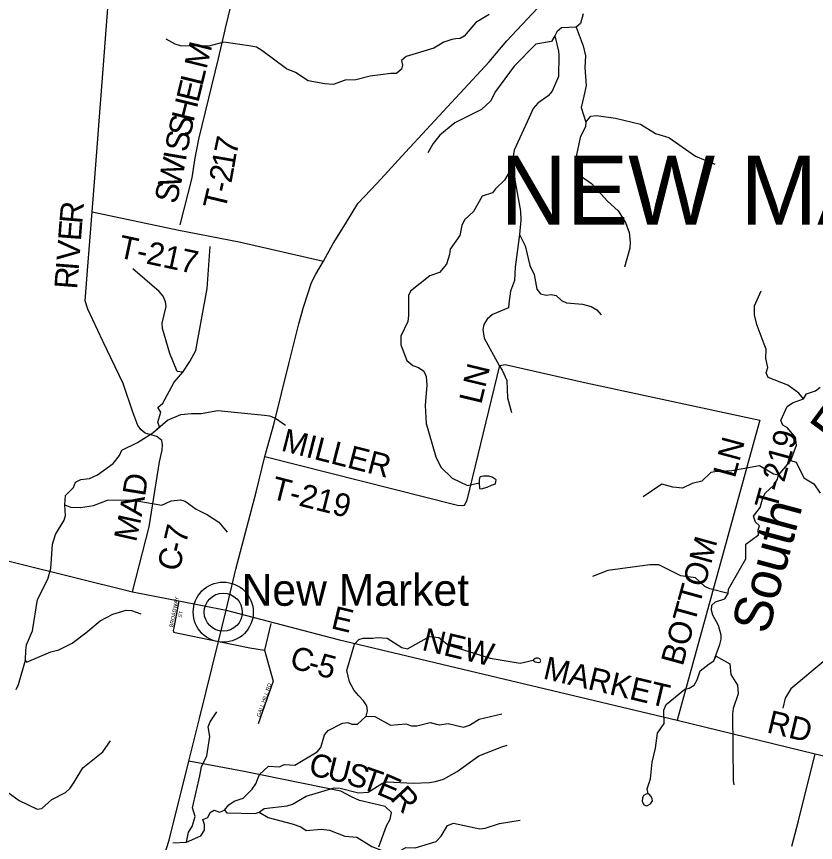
# Model space of a CAD drawing. Extents: x 1525783 to 1900577, y 218250 to 627376.
# Drawn here: x 1634317 to 1644767, y 412684 to 423483 of the extents above; entities that cross this region are included whole.
import ezdxf

# ---------------------------------------------------------------- set-up
doc = ezdxf.new("R2010")
doc.units = 0
for name, color, linetype in [('GM_X_County_Road', 7, 'Continuous'), ('GM_X_County_Road_Text', 7, 'Continuous'), ('GM_X_Minor_Lake', 7, 'Continuous'), ('GM_X_Minor_River', 7, 'Continuous'), ('GM_X_Minor_River_Text', 7, 'Continuous'), ('GM_X_Township_Road', 7, 'Continuous'), ('GM_X_Township_Road_Text', 7, 'Continuous'), ('GM_X_Township_ROW', 7, 'Continuous'), ('GM_X_Township_Subdivision', 7, 'Continuous'), ('GM_X_Township_Subdivision_Text', 7, 'Continuous'), ('GM_X_Township_Text', 7, 'Continuous'), ('GM_X_Unincorporated', 7, 'Continuous'), ('GM_X_Unincorporated_Location', 7, 'Continuous'), ('GM_X_Unincorporated_Text', 7, 'Continuous'), ('GM_X_US_Route', 7, 'Continuous')]:
    doc.layers.add(name, color=color, linetype=linetype)

msp = doc.modelspace()

# ---------------------------------------------------------------- linework, layer by layer
at = {"layer": 'GM_X_County_Road'}
for points in [[(1635835, 415961), (1636054, 416812), (1636189, 417660), (1636221, 417814), (1636227, 417882), (1636219, 417938), (1636154, 417994), (1636001, 418035), (1635948, 418078), (1635903, 418134), (1635838, 418312), (1635713, 418683), (1635446, 419238), (1635252, 419658), (1635217, 419764), (1635246, 420162), (1635307, 420930), (1635348, 421429), (1635515, 423648)], [(1631793, 415765), (1631793, 415765), (1631953, 416522), (1631988, 416688), (1632010, 416780), (1632047, 416831), (1632214, 416828), (1633533, 416532), (1635835, 415961), (1636440, 415843), (1637058, 415721)], [(1637058, 415721), (1637058, 415721), (1638525, 415336), (1642958, 414285), (1644763, 413844), (1647257, 413258)]]:
    msp.add_lwpolyline(points, dxfattribs=at)
at = {"layer": 'GM_X_Minor_Lake'}
for points in [[(1640393, 417306), (1640443, 417322), (1640473, 417331), (1640530, 417357), (1640580, 417374), (1640590, 417424), (1640539, 417459), (1640495, 417473), (1640425, 417472), (1640381, 417463), (1640371, 417447), (1640366, 417417), (1640368, 417387)], [(1640368, 417387), (1640374, 417311), (1640393, 417306)], [(1641075, 415068), (1641089, 415052), (1641101, 415046), (1641121, 415040), (1641147, 415035), (1641165, 415043), (1641173, 415057), (1641161, 415085), (1641138, 415094), (1641112, 415092), (1641099, 415088), (1641079, 415074)], [(1641079, 415074), (1641075, 415068)], [(1642553, 413317), (1642537, 413309), (1642519, 413297), (1642504, 413263), (1642500, 413223), (1642521, 413175), (1642563, 413164), (1642607, 413190), (1642634, 413229), (1642632, 413256), (1642616, 413286)], [(1642616, 413286), (1642592, 413315), (1642578, 413320), (1642553, 413317)]]:
    msp.add_lwpolyline(points, dxfattribs=at)
at = {"layer": 'GM_X_Minor_River'}
for points in [[(1640497, 423509), (1640324, 423405), (1640170, 423225), (1640119, 423194), (1640065, 423193), (1640009, 423181), (1639907, 423149), (1639776, 423070), (1639413, 422959), (1639353, 422910), (1639364, 422845), (1639353, 422793), (1639285, 422740), (1639211, 422739), (1638943, 422703), (1638756, 422655), (1638616, 422651), (1638458, 422595), (1638348, 422604), (1638131, 422643), (1637966, 422749), (1637849, 422801), (1637527, 423038), (1637455, 423081), (1637385, 423094), (1637027, 423146), (1636832, 423097), (1636461, 423098), (1636391, 423123), (1636274, 423188)], [(1641730, 423517), (1641692, 423392), (1641636, 423344), (1641446, 423335), (1641383, 423281), (1641358, 423230), (1641404, 423031), (1641411, 422979), (1641405, 422700), (1641321, 422507), (1641270, 422444), (1641135, 422351), (1641076, 422280), (1641023, 422163), (1640824, 421735), (1640785, 421491), (1640699, 421342), (1640582, 421231), (1640541, 421176), (1640406, 421133), (1640296, 420933), (1640177, 420824), (1640140, 420750), (1640114, 420622), (1639990, 420442), (1639979, 420372), (1639940, 420246), (1639850, 420137), (1639724, 420093), (1639470, 419890), (1639445, 419834), (1639445, 419572), (1639434, 419494), (1639344, 419303), (1639345, 419189), (1639420, 418987), (1639499, 418922), (1639575, 418893), (1639644, 418844), (1639673, 418778), (1639685, 418665), (1639662, 418397), (1639673, 418163), (1639801, 417727), (1639867, 417590), (1640015, 417449), (1640214, 417353), (1640368, 417387)], [(1641636, 423344), (1641730, 423099), (1641759, 422970), (1641751, 422818), (1641769, 422581), (1641736, 422442), (1641700, 422294), (1641763, 422103), (1641759, 422045), (1641691, 421902), (1641625, 421590), (1641618, 421512), (1641633, 421444), (1641839, 421299), (1642046, 421070), (1642184, 420944), (1642280, 420788), (1642328, 420658), (1642342, 420531), (1642337, 420453), (1642270, 420208)], [(1641358, 423230), (1641315, 423156), (1641109, 423121), (1640826, 422832), (1640580, 422503), (1640518, 422376), (1640399, 422269), (1640051, 422093), (1639855, 421932), (1639766, 421821), (1639695, 421701)], [(1641763, 422103), (1641830, 422178), (1641904, 422187), (1642152, 422156), (1642480, 422077), (1642676, 421955), (1642849, 421902), (1643196, 421659), (1643450, 421554)], [(1640785, 421491), (1640831, 421368), (1640907, 420939), (1640914, 420822), (1640897, 420634), (1640840, 420206), (1640832, 420030), (1640776, 419893), (1640758, 419729), (1640751, 419673), (1640542, 419585), (1640474, 419526), (1640429, 419455), (1640416, 419391), (1640432, 419278), (1640628, 418919), (1640667, 418861), (1640731, 418722), (1640738, 418497), (1640793, 418304)], [(1640897, 420634), (1640969, 420485), (1641030, 420228), (1641086, 420109), (1641124, 419920), (1641171, 419858), (1641243, 419841), (1641309, 419848), (1641374, 419835), (1641444, 419772), (1641509, 419739), (1641721, 419720), (1641834, 419693), (1641905, 419646), (1641964, 419581)], [(1636100, 418038), (1636187, 418117), (1636164, 418181), (1636207, 418309), (1636164, 418373), (1636231, 418428), (1636378, 418701), (1636494, 418834), (1636585, 418974), (1636663, 419116), (1636809, 419929), (1636850, 420475)], [(1636494, 418834), (1636418, 418841), (1636321, 419076), (1636225, 419406), (1636224, 419472), (1636273, 419690), (1636268, 419754), (1636235, 419826), (1636184, 419889), (1635840, 420186)], [(1644609, 418485), (1644548, 418558), (1644404, 418664), (1644147, 418765), (1644120, 418826), (1644145, 418893), (1644116, 419010), (1644120, 419134), (1644097, 419198), (1644004, 419444), (1643970, 419579), (1643970, 419701), (1644054, 419896)], [(1642578, 413320), (1642566, 413385), (1642611, 413518), (1642630, 413734), (1642674, 413918), (1642699, 414112), (1642786, 414241), (1642785, 414415), (1642814, 414487), (1643056, 414690), (1643116, 414703), (1643182, 414742), (1643221, 414812), (1643257, 414928), (1643378, 415018), (1643436, 415061), (1643515, 415271), (1643534, 415341), (1643534, 415393), (1643500, 415523), (1643426, 415656), (1643407, 415721), (1643410, 415785), (1643460, 415830), (1643581, 415871), (1643623, 415938), (1643630, 415998), (1643857, 416394), (1643857, 416584), (1644023, 416708), (1644016, 416772), (1644034, 416826), (1643981, 416873), (1643956, 416949), (1644045, 417062), (1644079, 417190), (1644114, 417256), (1644221, 417354), (1644270, 417432), (1644285, 417486), (1644443, 417680), (1644519, 417877), (1644507, 417979), (1644400, 418107), (1644339, 418140), (1644314, 418200), (1644396, 418385), (1644467, 418434), (1644609, 418485), (1644648, 418548), (1644766, 418589), (1644827, 418636)], [(1634311, 414684), (1634345, 414748), (1634437, 415067), (1634439, 415197), (1634448, 415269), (1634526, 415451), (1634593, 415862), (1634725, 416127), (1634768, 416267), (1634787, 416583), (1634828, 416710), (1634940, 416897), (1634957, 416959), (1634951, 417097), (1634957, 417221), (1635064, 417326), (1635089, 417394), (1635159, 417431), (1635273, 417444), (1635378, 417492), (1635581, 417640), (1635664, 417743), (1635695, 417813), (1635900, 417912), (1636100, 418038), (1636294, 418205), (1636466, 418279), (1636606, 418291), (1636734, 418294), (1636952, 418331), (1637561, 418269), (1637627, 418262), (1637706, 418231), (1637837, 418139)], [(1644285, 417486), (1644217, 417500), (1644034, 417607), (1643674, 417544), (1643450, 417531), (1643400, 417521), (1643281, 417409), (1643153, 417378), (1643028, 417318), (1642900, 417328), (1642755, 417367), (1642515, 417202)], [(1644443, 417680), (1644516, 417655), (1644616, 417451), (1644745, 417373), (1644827, 417252)], [(1634951, 417097), (1635025, 417070), (1635154, 417065), (1635326, 417092), (1635507, 417160), (1635819, 417164), (1636217, 417095), (1636340, 417153), (1636460, 417162), (1636522, 417145), (1636668, 417041), (1636817, 416969), (1636962, 416871), (1637072, 416741)], [(1643623, 415938), (1643384, 416001), (1643321, 416032), (1643197, 416142), (1643007, 416169), (1642719, 416314), (1642602, 416316), (1642053, 416239), (1641852, 416160)], [(1634437, 415067), (1634449, 415041), (1634768, 415177), (1634871, 415202), (1635046, 415292), (1635223, 415426), (1635413, 415581), (1635578, 415671), (1635750, 415723), (1635822, 415716), (1635943, 415672)], [(1636362, 412679), (1636540, 412689), (1636729, 412772), (1636776, 412846), (1636775, 412920), (1636752, 412986), (1636820, 413009), (1636851, 413075), (1636903, 413106), (1636973, 413079), (1637037, 413105), (1637096, 413178), (1637164, 413225), (1637281, 413262), (1637400, 413380), (1637449, 413452), (1637468, 413506), (1637494, 413575), (1637612, 413680), (1637757, 413674), (1637820, 413703), (1637959, 413695), (1638251, 413868), (1638296, 413927), (1638344, 414091), (1638395, 414148), (1638582, 414242), (1638652, 414251), (1638703, 414230), (1638775, 414229), (1638890, 414336), (1638909, 414406), (1638900, 414470), (1638855, 414537), (1638796, 414600), (1638735, 414669), (1638673, 414785), (1638636, 414932), (1638739, 415277), (1638796, 415337), (1638850, 415354), (1638978, 415356), (1639036, 415366), (1639163, 415356), (1639358, 415235), (1639429, 415216), (1639719, 415379), (1639839, 415363), (1639969, 415265), (1640512, 415094), (1640905, 415029), (1641075, 415068)], [(1643436, 415061), (1643469, 415121), (1643645, 415019), (1643658, 414882), (1643748, 414739), (1643754, 414629), (1643688, 414435), (1643681, 414365), (1643692, 413496), (1643697, 413438)], [(1644895, 415066), (1644444, 414692), (1644369, 414569), (1644339, 414439)], [(1636540, 412689), (1636568, 412820), (1636615, 412894), (1636654, 413022), (1636620, 413136), (1636717, 413557), (1636735, 413675), (1636806, 413815), (1636846, 414068), (1636825, 414195), (1636848, 414261), (1636938, 414390)], [(1638890, 414336), (1639004, 414329), (1639209, 414220), (1639407, 414235), (1639484, 414210), (1639554, 414211), (1639726, 414253), (1639846, 414223), (1639964, 414240), (1640165, 414191), (1640241, 414216), (1640370, 414295), (1640663, 414365)], [(1633271, 413396), (1633308, 413448), (1633716, 413352), (1634092, 413390), (1634162, 413371), (1634350, 413232), (1634588, 413121), (1634648, 413128), (1634779, 413248), (1634956, 413338), (1635021, 413393), (1635070, 413473), (1635186, 413660), (1635445, 413869), (1635546, 414011)], [(1637037, 413105), (1637070, 413072), (1637440, 413065), (1637492, 413079), (1637557, 413128), (1637859, 413162), (1637927, 413187), (1638104, 413291), (1638473, 413400), (1638549, 413395), (1638788, 413332), (1638918, 413344), (1639105, 413460), (1639169, 413477), (1639504, 413459), (1639718, 413468), (1639796, 413483), (1639901, 413512), (1640080, 413611), (1640364, 413818), (1640665, 413936), (1640733, 413955)], [(1637492, 413079), (1637609, 413009), (1637923, 412929), (1638035, 412887), (1638106, 412840), (1638302, 412858), (1638410, 412844), (1638613, 412768), (1638770, 412755), (1638966, 412631), (1639098, 412579), (1639295, 412554), (1639410, 412617), (1639531, 412613), (1639806, 412696), (1639871, 412767), (1639953, 412904), (1640033, 412937), (1640376, 412863), (1640448, 412870), (1640634, 412931), (1640904, 412974)]]:
    msp.add_lwpolyline(points, dxfattribs=at)
at = {"layer": 'GM_X_Township_Road'}
for points in [[(1637052, 423329), (1637278, 424268), (1637278, 424365), (1637278, 424369)], [(1636458, 420759), (1636615, 421373), (1636651, 421611), (1636701, 421880), (1636957, 422934), (1637048, 423310), (1637052, 423329)], [(1635307, 420930), (1636440, 420688), (1637228, 420536), (1638334, 420284)], [(1637564, 417732), (1640083, 417093), (1640146, 417089), (1640167, 417094), (1640178, 417096), (1640212, 417161), (1640639, 418920), (1640710, 418934), (1641768, 418694)], [(1643987, 418020), (1642958, 414285)], [(1644458, 412634), (1644458, 412636), (1644544, 412968), (1644763, 413844)], [(1639058, 412625), (1639157, 412900), (1639202, 412989), (1639220, 413077), (1639137, 413155), (1638991, 413190), (1638805, 413233), (1638699, 413283), (1638560, 413354), (1637295, 413611), (1636573, 413748)]]:
    msp.add_lwpolyline(points, dxfattribs=at)
at = {"layer": 'GM_X_Township_ROW'}
msp.add_lwpolyline([(1641768, 418694), (1641890, 418666), (1644038, 418206), (1643987, 418020)], dxfattribs=at)
at = {"layer": 'GM_X_Township_Subdivision'}
for points in [[(1636440, 415843), (1636373, 415492), (1636364, 415456), (1636370, 415434), (1636959, 415313)], [(1637643, 415546), (1637559, 415199), (1637673, 414794), (1637479, 414237)], [(1636959, 415313), (1636960, 415313), (1636964, 415312), (1637367, 415230), (1637559, 415199)]]:
    msp.add_lwpolyline(points, dxfattribs=at)
at = {"layer": 'GM_X_Unincorporated'}
for radius in [393, 249]:
    msp.add_circle((1637021, 415695), radius, dxfattribs=at)
at = {"layer": 'GM_X_Unincorporated_Location'}
msp.add_line((1637021, 415695), (1637021, 415695), dxfattribs=at)
at = {"layer": 'GM_X_US_Route'}
for points in [[(1640793, 423231), (1641549, 424042), (1641888, 424416), (1642101, 424640), (1642269, 424800), (1642396, 424895), (1642540, 424992), (1642685, 425067), (1642874, 425142), (1642996, 425178), (1643094, 425203), (1643201, 425221), (1643683, 425274), (1644766, 425393), (1645503, 425474), (1645766, 425521), (1645969, 425576), (1646183, 425637), (1646335, 425694)], [(1639406, 421710), (1639678, 422005), (1640497, 422890), (1640731, 423164), (1640793, 423231)], [(1636710, 414304), (1636960, 415313), (1637058, 415721), (1637187, 416256), (1637450, 417266), (1637564, 417732), (1637686, 418168), (1637877, 418940), (1638010, 419463), (1638071, 419681), (1638130, 419870), (1638176, 420004), (1638232, 420116), (1638334, 420284), (1638460, 420516), (1638618, 420774), (1638783, 421038), (1639032, 421304), (1639406, 421710)], [(1634007, 402550), (1634160, 403228), (1634285, 403847), (1634362, 404367), (1634469, 405154), (1634564, 405879), (1634769, 407238), (1634853, 407802), (1634911, 408078), (1635027, 408481), (1635129, 408723), (1635509, 409998), (1635742, 410794), (1636081, 411975), (1636179, 412290), (1636314, 412715), (1636573, 413748), (1636710, 414304)]]:
    msp.add_lwpolyline(points, dxfattribs=at)

# ---------------------------------------------------------------- texts
at = {"layer": 'GM_X_County_Road_Text'}
for s, rotation, p in [('R', 84.8723, (1635176, 420765)), ('E', 85.5794, (1635159, 420542)), ('V', 85.6016, (1635139, 420279)), ('R', 85.601, (1635110, 419911)), ('I', 85.6014, (1635129, 420156)), ('D', 80.8503, (1635998, 417200)), ('A', 80.5693, (1635954, 416938)), ('M', 77.3643, (1635880, 416602)), ('7', 76.7023, (1636533, 416578)), ('C', 75.8511, (1636442, 416214)), ('-', 75.9507, (1636502, 416454)), ('E', 346.4029, (1638418, 415487)), ('NEW', 346.6218, (1639607, 415203)), ('C', 344.5854, (1637875, 414973)), ('5', 345.0259, (1638233, 414874)), ('MARKET', 346.6753, (1641191, 414829)), ('-', 344.6259, (1638112, 414907)), ('RD', 346.5615, (1644117, 414125))]:
    msp.add_text(s, height=300, rotation=rotation, dxfattribs=at).set_placement(p)
at = {"layer": 'GM_X_Minor_River_Text'}
for s, height, rotation, p in [('Fork', 500, 53.5142, (1645067, 417831)), ('South', 500.1, 74.9616, (1644146, 415393))]:
    msp.add_text(s, height=height, rotation=rotation, dxfattribs=at).set_placement(p)
at = {"layer": 'GM_X_Township_Road_Text'}
for s, rotation, p in [('M', 76.251, (1636801, 422784)), ('L', 76.2536, (1636748, 422566)), ('E', 76.2506, (1636695, 422348)), ('H', 76.3021, (1636632, 422092)), ('S', 77.2764, (1636588, 421896)), ('S', 79.2823, (1636551, 421700)), ('7', 78.1553, (1637192, 421660)), ('I', 80.2481, (1636530, 421580)), ('W', 78.205, (1636457, 421228)), ('1', 80.156, (1637161, 421481)), ('2', 79.5195, (1637127, 421296)), ('S', 76.3636, (1636407, 421021)), ('-', 77.7908, (1637099, 421166)), ('T', 76.5354, (1637045, 420941)), ('T-217', 347.8736, (1635631, 420335)), ('LN', 76.4634, (1640394, 418402)), ('MILLER', 345.6048, (1637765, 417810)), ('T-219', 74.6712, (1644257, 417018)), ('LN', 74.8347, (1643712, 417438)), ('T-219', 345.8279, (1637630, 417183)), ('BOTTOM', 74.5021, (1643030, 414979)), ('C', 348.0046, (1638126, 413567)), ('U', 346.1241, (1638364, 413516)), ('S', 342.5305, (1638616, 413454)), ('T', 341.0074, (1638807, 413394)), ('E', 336.715, (1639013, 413323)), ('R', 312.514, (1639192, 413254))]:
    msp.add_text(s, height=300, rotation=rotation, dxfattribs=at).set_placement(p)
at = {"layer": 'GM_X_Township_Subdivision_Text'}
for s, rotation, p in [('BROADWAY', 78.8271, (1636363, 415495)), ('ST', 79.3853, (1636478, 415619)), ('GALL HILL RD', 70.994, (1637503, 414321))]:
    msp.add_text(s, height=50, rotation=rotation, dxfattribs=at).set_placement(p)
at = {"layer": 'GM_X_Township_Text'}
msp.add_text('NEW MARKET', height=900, rotation=0, dxfattribs=at).set_placement((1640645, 420762))
at = {"layer": 'GM_X_Unincorporated_Text'}
msp.add_text('New Market', height=417, rotation=0, dxfattribs=at).set_placement((1637261, 415779))

doc.saveas('drawing.dxf')
